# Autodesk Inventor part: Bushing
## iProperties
Shininess: 77.0
Length Units: 11269
Angle Units: 11279
Time Units: 11290
Mass Units: 11283
Length Display Precision: 3
Angle Display Precision: 2
Created: 2002-02
Part Number: Bushing
Document SubType Name: Modeling
Designer: ***
Density: 0.0
Volumn: 0.0
Area: 0.0
PropertySet Name: Model Information
Control State: 0
Master: False
Checked Out: False
Author: ***
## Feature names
1. Revolution1
